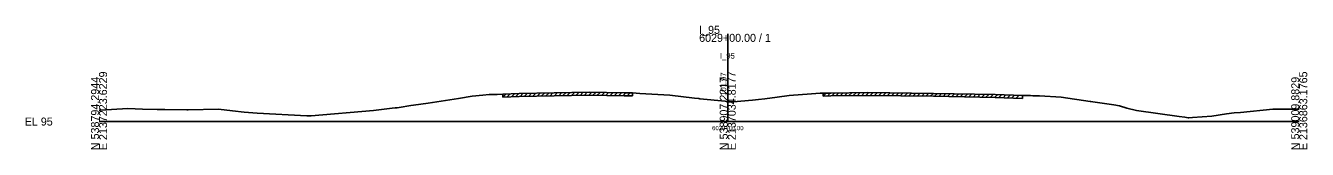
# Model space of a CAD drawing. Extents: x -12534 to 3403, y -1332 to 21983.
# Drawn here: x 974.3 to 1422.8, y 15990.3 to 16033.5 of the extents above; entities that cross this region are included whole.
import ezdxf

# ---------------------------------------------------------------- set-up
doc = ezdxf.new("R2010")
doc.units = 0
for name, color, linetype in [('RD_GPK_XS_Cell', 7, 'Continuous'), ('RD_XS_ExGround', 7, 'Continuous'), ('RD_XS_ExPaveRet', 7, 'Continuous'), ('RD_XS_TX_Baseline', 7, 'Continuous'), ('RD_XS_TX_Elev_EX', 7, 'Continuous'), ('RD_XS_TX_Station', 7, 'Continuous')]:
    doc.layers.add(name, color=color, linetype=linetype)

msp = doc.modelspace()

# ---------------------------------------------------------------- linework, layer by layer
at = {"layer": 'RD_GPK_XS_Cell'}
for p, q in [((1220, 16000), (1220, 16030.62)), ((1000, 16000), (1220, 16000)), ((1220, 16000), (1420, 16000))]:
    msp.add_line(p, q, dxfattribs=at)
at = {"layer": 'RD_XS_ExGround'}
msp.add_lwpolyline([(1000, 16003.94), (1000.47, 16003.98), (1010.03, 16004.56), (1015.21, 16004.3), (1020.33, 16004.15), (1022.97, 16004.2), (1030.66, 16004.13), (1031.21, 16004.13), (1041.75, 16004.32), (1046.67, 16003.74), (1050.74, 16003.28), (1055.34, 16002.87), (1072.71, 16001.95), (1073.13, 16001.95), (1074.19, 16002.05), (1095.99, 16003.84), (1099.73, 16004.31), (1102.56, 16004.7), (1103.64, 16004.75), (1104.38, 16004.84), (1105.01, 16004.93), (1109.05, 16005.56), (1110.05, 16005.69), (1115.13, 16006.46), (1125.75, 16008.09), (1130.55, 16008.82), (1134.35, 16009.25), (1136.5, 16009.42), (1139.28, 16009.49), (1141.34, 16009.56), (1146.98, 16009.79), (1171.49, 16010.21), (1183.79, 16010.02), (1186.72, 16009.98), (1189.22, 16009.83), (1199.77, 16009.2), (1208.42, 16008.19), (1209.87, 16008.03), (1210.28, 16007.96), (1219.07, 16007.07), (1220, 16006.97), (1220.39, 16006.93), (1221.2, 16006.84), (1221.94, 16006.86), (1228.64, 16007.45), (1230.75, 16007.7), (1232.98, 16007.96), (1237.27, 16008.52), (1241.54, 16009.1), (1249.27, 16009.64), (1252.35, 16009.86), (1253.38, 16009.89), (1256.1, 16009.93), (1269.06, 16010.15), (1292, 16009.84), (1313.63, 16009.39), (1323.13, 16009.1), (1325.91, 16009.05), (1326.8, 16009.02), (1329.06, 16008.92), (1336.66, 16008.46), (1346.79, 16007), (1347.12, 16006.96), (1347.79, 16006.87), (1355.1, 16005.8), (1357.07, 16005.45), (1359.7, 16004.71), (1363.09, 16003.89), (1377.93, 16001.79), (1379.91, 16001.48), (1381.09, 16001.3), (1381.41, 16001.32), (1382.7, 16001.44), (1389.39, 16001.83), (1394.52, 16002.64), (1397.21, 16003.07), (1399.48, 16003.18), (1410.79, 16004.31), (1411.21, 16004.31), (1420, 16004.33)], dxfattribs=at)
at = {"layer": 'RD_XS_ExPaveRet'}
for p, q in [((1141.34, 16008.56), (1142.38, 16009.6)), ((1141.34, 16008.56), (1141.34, 16009.56)), ((1141.34, 16008.56), (1146.98, 16008.79)), ((1142.84, 16008.62), (1143.88, 16009.66)), ((1144.34, 16008.68), (1145.38, 16009.72)), ((1145.84, 16008.74), (1146.88, 16009.78)), ((1146.98, 16008.79), (1171.49, 16009.21)), ((1147.34, 16008.79), (1148.35, 16009.81)), ((1148.84, 16008.82), (1149.85, 16009.84)), ((1150.34, 16008.84), (1151.35, 16009.86)), ((1151.84, 16008.87), (1152.85, 16009.89)), ((1153.34, 16008.9), (1154.35, 16009.91)), ((1154.84, 16008.92), (1155.85, 16009.94)), ((1156.34, 16008.95), (1157.35, 16009.96)), ((1157.84, 16008.97), (1158.85, 16009.99)), ((1159.34, 16009), (1160.35, 16010.02)), ((1160.84, 16009.02), (1161.85, 16010.04)), ((1162.34, 16009.05), (1163.35, 16010.07)), ((1163.84, 16009.08), (1164.85, 16010.09)), ((1165.34, 16009.1), (1166.35, 16010.12)), ((1166.84, 16009.13), (1167.85, 16010.15)), ((1168.34, 16009.15), (1169.35, 16010.17)), ((1169.84, 16009.18), (1170.85, 16010.2)), ((1171.34, 16009.2), (1172.33, 16010.19)), ((1171.49, 16009.21), (1183.79, 16009.02)), ((1172.84, 16009.19), (1173.82, 16010.17)), ((1174.34, 16009.16), (1175.32, 16010.15)), ((1175.84, 16009.14), (1176.82, 16010.13)), ((1177.34, 16009.12), (1178.32, 16010.1)), ((1178.84, 16009.1), (1179.82, 16010.08)), ((1180.34, 16009.07), (1181.32, 16010.06)), ((1181.84, 16009.05), (1182.82, 16010.04)), ((1183.34, 16009.03), (1184.32, 16010.01)), ((1183.79, 16009.02), (1186.72, 16008.98)), ((1184.84, 16009.01), (1185.82, 16010)), ((1186.72, 16009.98), (1186.72, 16008.98)), ((1253.38, 16008.89), (1254.39, 16009.9)), ((1253.38, 16008.89), (1253.38, 16009.89)), ((1253.38, 16008.89), (1256.1, 16008.93)), ((1254.88, 16008.91), (1255.89, 16009.93)), ((1256.1, 16008.93), (1269.06, 16009.15)), ((1256.38, 16008.93), (1257.39, 16009.95)), ((1257.88, 16008.96), (1258.89, 16009.98)), ((1259.38, 16008.98), (1260.39, 16010)), ((1260.88, 16009.01), (1261.89, 16010.03)), ((1262.38, 16009.04), (1263.39, 16010.05)), ((1263.88, 16009.06), (1264.89, 16010.08)), ((1265.38, 16009.09), (1266.39, 16010.1)), ((1266.88, 16009.11), (1267.89, 16010.13)), ((1268.38, 16009.14), (1269.38, 16010.14)), ((1269.06, 16009.15), (1292, 16008.84)), ((1269.88, 16009.14), (1270.86, 16010.12)), ((1271.38, 16009.12), (1272.36, 16010.1)), ((1272.88, 16009.1), (1273.86, 16010.08)), ((1274.38, 16009.08), (1275.36, 16010.06)), ((1275.88, 16009.06), (1276.86, 16010.04)), ((1277.38, 16009.04), (1278.36, 16010.02)), ((1278.88, 16009.02), (1279.86, 16010)), ((1280.38, 16009), (1281.36, 16009.98)), ((1281.88, 16008.98), (1282.86, 16009.96)), ((1283.38, 16008.96), (1284.36, 16009.94)), ((1284.88, 16008.94), (1285.86, 16009.92)), ((1286.38, 16008.92), (1287.36, 16009.9)), ((1287.88, 16008.9), (1288.86, 16009.88)), ((1289.38, 16008.88), (1290.36, 16009.86)), ((1290.88, 16008.86), (1291.86, 16009.84)), ((1292, 16008.84), (1313.63, 16008.39)), ((1292.38, 16008.83), (1293.36, 16009.81)), ((1293.88, 16008.8), (1294.86, 16009.78)), ((1295.38, 16008.77), (1296.36, 16009.75)), ((1296.88, 16008.74), (1297.86, 16009.72)), ((1298.38, 16008.71), (1299.36, 16009.69)), ((1299.88, 16008.68), (1300.86, 16009.66)), ((1301.38, 16008.65), (1302.36, 16009.63)), ((1302.88, 16008.61), (1303.86, 16009.59)), ((1304.38, 16008.58), (1305.36, 16009.56)), ((1305.88, 16008.55), (1306.86, 16009.53)), ((1307.38, 16008.52), (1308.36, 16009.5)), ((1308.88, 16008.49), (1309.86, 16009.47)), ((1310.38, 16008.46), (1311.36, 16009.44)), ((1311.88, 16008.43), (1312.86, 16009.41)), ((1313.38, 16008.4), (1314.35, 16009.37)), ((1313.63, 16008.39), (1323.13, 16008.1)), ((1314.88, 16008.35), (1315.85, 16009.32)), ((1316.38, 16008.31), (1317.35, 16009.28)), ((1317.88, 16008.26), (1318.85, 16009.23)), ((1319.38, 16008.22), (1320.35, 16009.19)), ((1320.88, 16008.17), (1321.85, 16009.14)), ((1323.13, 16009.1), (1323.13, 16008.1))]:
    msp.add_line(p, q, dxfattribs=at)

# ---------------------------------------------------------------- texts
at = {"layer": 'RD_GPK_XS_Cell'}
for s, p in [('6029+00.00 / 1', (1210, 16027.82)), ('I_95', (1210, 16030.62)), ('EL 95', (974, 15998.6))]:
    msp.add_text(s, height=2.8, dxfattribs=at).set_placement(p)
for s, p in [('E 2137223.6229', (1002.8, 15990)), ('E 2137034.8177', (1222.8, 15990)), ('E 2136863.1765', (1422.8, 15990)), ('N 538794.2944', (1000, 15990)), ('N 538907.2217', (1220, 15990)), ('N 539009.8829', (1420, 15990))]:
    msp.add_text(s, height=2.8, rotation=90, dxfattribs=at).set_placement(p)
at = {"layer": 'RD_XS_TX_Baseline'}
msp.add_text('I_95', height=2, dxfattribs=at).set_placement((1217.28, 16021.97))
at = {"layer": 'RD_XS_TX_Elev_EX'}
msp.add_text('101.97', height=2, rotation=90, dxfattribs=at).set_placement((1219.5, 16008.97))
at = {"layer": 'RD_XS_TX_Station'}
msp.add_text('6029+00.00', height=1.5, dxfattribs=at).set_placement((1214.54, 15996.97))

doc.saveas('drawing.dxf')
